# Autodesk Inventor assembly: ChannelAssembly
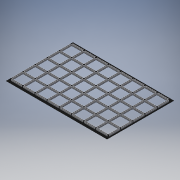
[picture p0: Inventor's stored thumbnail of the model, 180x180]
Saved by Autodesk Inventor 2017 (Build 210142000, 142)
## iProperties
Created: 2017-05
Part Number: ChannelAssembly
Document SubType Name: Assembly
Designer: Savy
Author: Savy
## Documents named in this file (4)
- D:\Users\Savy\Documents\Infinity Table\ChannelAssembly.iam
- D:\Users\Savy\Documents\Infinity Table\UChannel.ipt
- D:\Users\Savy\Documents\Infinity Table\LEDStrip.ipt
- D:\Users\Savy\Documents\Infinity Table\TopCutout_Cover.ipt
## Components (103 placed, 102 different names)
1. UChannel_1023
2. UChannel_1024
3. UChannel_1026
4. UChannel_1027
5. UChannel_1029
6. UChannel_1030
7. UChannel_1032
8. UChannel_1033
9. UChannel_1035 — Mate:2
10. UChannel_1036
11. UChannel_1038
12. UChannel_1039
13. UChannel_1041
14. UChannel_1042
15. UChannel_1044
16. UChannel_1045
17. UChannel_1047
18. UChannel_1048
19. UChannel_1050
20. UChannel_1051
21. UChannel_1053
22. UChannel_1054
23. UChannel_1056
24. UChannel_1057
25. UChannel_1059
26. UChannel_1060
27. UChannel_1062
28. UChannel_1063
29. UChannel_1065
30. UChannel_1066
31. UChannel_1068
32. UChannel_1069
33. UChannel_1071
34. UChannel_1072
35. UChannel_1074
36. UChannel_1075
37. UChannel_1077
38. UChannel_1078
39. UChannel_1080
40. UChannel_1081
41. UChannel_1083
42. UChannel_1084
43. UChannel_1086
44. UChannel_1087
45. UChannel_1089
46. UChannel_1090
47. UChannel_1092
48. UChannel_1093
49. UChannel_1095
50. UChannel_1096
51. UChannel_1098
52. UChannel_1099
53. UChannel_1101
54. UChannel_1102
55. UChannel_1104
56. UChannel_1105
57. UChannel_1107
58. UChannel_1108
59. UChannel_1110
60. UChannel_1111
61. UChannel_1113
62. UChannel_1114
63. UChannel_1116
64. UChannel_1117
65. UChannel_1119
66. UChannel_1120
67. UChannel_1122
68. UChannel_1123
69. UChannel_1125
70. UChannel_1126
71. UChannel_1128
72. UChannel_1129 — Flush:2
73. UChannel_1131
74. UChannel_1132
75. UChannel_1134
76. UChannel_1135
77. UChannel_1137
78. UChannel_1138
79. UChannel_1140
80. UChannel_1141
81. UChannel_1143
82. UChannel_1145
83. UChannel_1147
84. UChannel_1149 — Mate:1
85. UChannel_1151
86. UChannel_1153
87. UChannel_1155
88. UChannel_1157
89. UChannel_1159
90. UChannel_1161
91. UChannel_1163
92. UChannel_1165
93. UChannel_1167 — Flush:1
94. LEDStrip_1169
95. LEDStrip_1170
96. LEDStrip_1171
97. LEDStrip_1172
98. LEDStrip_1173
99. LEDStrip_1174
100. LEDStrip_1175
101. LEDStrip_1176
102. TopCutout_Cover:1 — Mate:1, Flush:1, Flush:2, Mate:3, Flush:3
103. TopCutout_Cover:2 — Mate:2, Mate:3, Flush:3
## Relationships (6: Mate 3, Flush 3)
- Mate:1: UChannel_1149 ↔ TopCutout_Cover:1
- Flush:1: UChannel_1167 ↔ TopCutout_Cover:1
- Flush:2: UChannel_1129 ↔ TopCutout_Cover:1
- Mate:2: UChannel_1035 ↔ TopCutout_Cover:2
- Mate:3: TopCutout_Cover:1 ↔ TopCutout_Cover:2
- Flush:3: TopCutout_Cover:1 ↔ TopCutout_Cover:2
